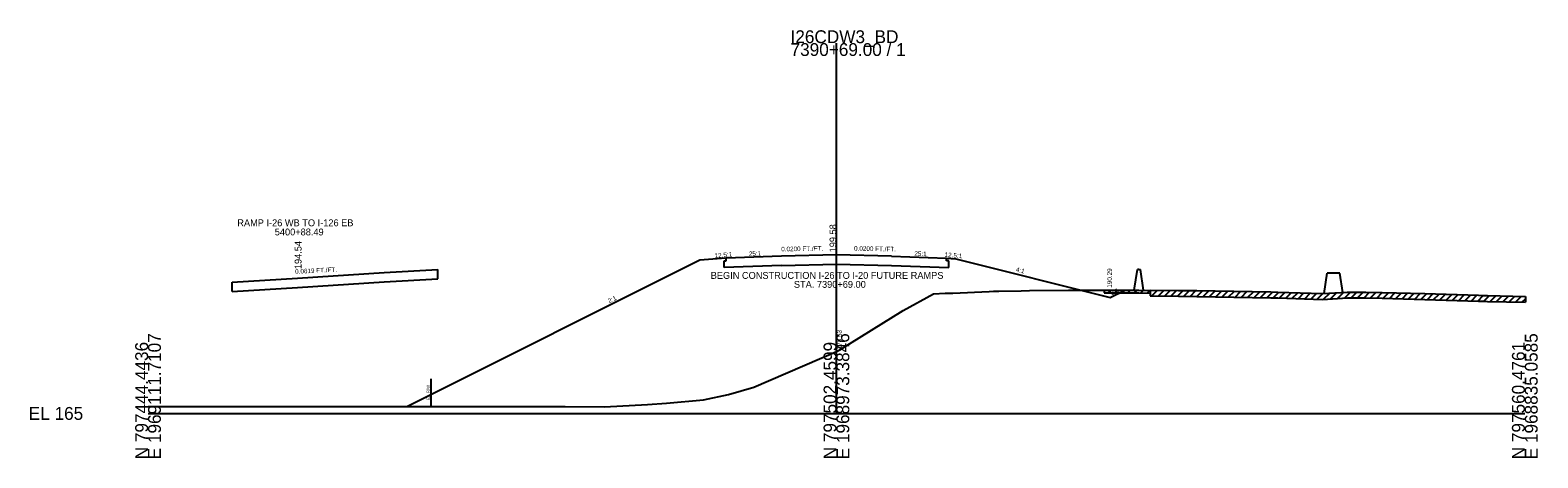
# Model space of a CAD drawing. Extents: x -26 to 1968923, y -11 to 797553.
# Drawn here: x 24.3 to 352.8, y -10.7 to 82.6 of the extents above; entities that cross this region are included whole.
import ezdxf

# ---------------------------------------------------------------- set-up
doc = ezdxf.new("R2010")
doc.units = 0
for name, color, linetype in [('RD_GPK_XS_Cell', 7, 'Continuous'), ('RD_XS_Base', 7, 'Continuous'), ('RD_XS_Bridge', 7, 'Continuous'), ('RD_XS_EarthShd', 7, 'Continuous'), ('RD_XS_ExGround', 7, 'Continuous'), ('RD_XS_ExPaveRet', 7, 'Continuous'), ('RD_XS_ExRW', 7, 'Continuous'), ('RD_XS_MedBWall', 7, 'Continuous'), ('RD_XS_Misc_Line', 7, 'Continuous'), ('RD_XS_Pave', 7, 'Continuous'), ('RD_XS_PaveShd', 7, 'Continuous'), ('RD_XS_TieSlope', 7, 'Continuous'), ('RD_XS_TX_Elev_EX', 7, 'Continuous'), ('RD_XS_TX_Elev_PR', 7, 'Continuous'), ('RD_XS_TX_Notes', 7, 'Continuous'), ('RD_XS_TX_Profile', 7, 'Continuous'), ('RD_XS_TX_ShdSlope', 7, 'Continuous'), ('RD_XS_TX_Slope', 7, 'Continuous'), ('RD_XS_TX_Station', 7, 'Continuous')]:
    doc.layers.add(name, color=color, linetype=linetype)

msp = doc.modelspace()

# ---------------------------------------------------------------- linework, layer by layer
at = {"layer": 'RD_GPK_XS_Cell'}
for p, q in [((200, -1), (200, 79.77)), ((50, -1), (200, -1)), ((200, -1), (350, -1))]:
    msp.add_line(p, q, dxfattribs=at)
at = {"layer": 'RD_XS_Base'}
for p, q in [((176, 32.3), (176, 32.86)), ((224, 32.3), (224, 32.86)), ((175.5, 32.28), (176, 32.3)), ((175.5, 30.8), (175.5, 32.28)), ((188, 31.3), (175.5, 30.8)), ((188, 31.3), (200, 31.54)), ((200, 31.54), (212, 31.3)), ((212, 31.3), (224.5, 30.8)), ((224.5, 32.28), (224, 32.3)), ((224.5, 30.8), (224.5, 32.28))]:
    msp.add_line(p, q, dxfattribs=at)
at = {"layer": 'RD_XS_Bridge'}
for p, q in [((82.57, 28.54), (101.43, 29.71)), ((101.43, 29.71), (113.12, 30.43)), ((113.12, 28.39), (113.12, 30.43)), ((68.3, 27.66), (82.57, 28.54)), ((68.3, 25.62), (68.3, 27.66)), ((68.3, 25.62), (82.57, 26.5)), ((82.57, 26.5), (101.43, 27.67)), ((101.43, 27.67), (113.12, 28.39))]:
    msp.add_line(p, q, dxfattribs=at)
at = {"layer": 'RD_XS_EarthShd'}
for p, q in [((176, 32.86), (174, 32.7)), ((224, 32.86), (226, 32.7))]:
    msp.add_line(p, q, dxfattribs=at)
at = {"layer": 'RD_XS_ExGround'}
msp.add_lwpolyline([(50, 0.54), (51.32, 0.54), (57.94, 0.54), (61.61, 0.54), (62.74, 0.54), (68.6, 0.54), (84.4, 0.54), (101.34, 0.54), (105.3, 0.54), (121.41, 0.54), (132.82, 0.54), (133.91, 0.54), (135.83, 0.54), (139.98, 0.54), (140.35, 0.54), (140.86, 0.53), (149.45, 0.46), (158.82, 0.95), (162.99, 1.27), (171.03, 2), (176.45, 3.1), (181.99, 4.7), (200, 12.53), (200.71, 12.84), (214.55, 21.44), (221.14, 25.06), (223.68, 25.21), (225.33, 25.26), (233.27, 25.63), (234.2, 25.68), (234.61, 25.69), (235.04, 25.69), (235.4, 25.68), (240.28, 25.75), (242.04, 25.79), (250.56, 25.9), (252.17, 25.9), (265.9, 25.92), (274.56, 25.8), (278.55, 25.79), (294.68, 25.49), (296.2, 25.48), (305.93, 25.13), (311.29, 25.46), (312.47, 25.48), (314.53, 25.46), (315.39, 25.45), (318.94, 25.37), (328.22, 25.13), (339.92, 24.77), (340.97, 24.73), (341.88, 24.7), (350.14, 24.49)], dxfattribs=at)
at = {"layer": 'RD_XS_ExPaveRet'}
for p, q in [((258.37, 25.91), (258.37, 25.29)), ((268.37, 25.89), (268.37, 24.64)), ((350.14, 24.49), (350.14, 23.24))]:
    msp.add_line(p, q, dxfattribs=at)
for points in [[(258.37, 25.29), (265.89, 25.3), (268.37, 25.26)], [(268.37, 24.64), (274.55, 24.55), (278.54, 24.54), (294.67, 24.24), (296.18, 24.23), (305.95, 23.88), (311.34, 24.21), (312.47, 24.23), (314.52, 24.21), (315.37, 24.2), (318.91, 24.12), (328.19, 23.88), (339.88, 23.52), (340.93, 23.48), (341.85, 23.45), (350.14, 23.24)]]:
    msp.add_lwpolyline(points, dxfattribs=at)
at = {"layer": 'RD_XS_ExRW'}
msp.add_line((111.6, 6.54), (111.6, 0.54), dxfattribs=at)
at = {"layer": 'RD_XS_MedBWall'}
for p, q in [((264.9, 25.92), (265.57, 30.4)), ((265.9, 30.4), (265.57, 30.4)), ((265.9, 30.4), (266.23, 30.4)), ((266.9, 25.92), (266.23, 30.4)), ((306.28, 25.15), (306.95, 29.63)), ((309.72, 29.63), (306.95, 29.63)), ((310.35, 25.4), (309.72, 29.63))]:
    msp.add_line(p, q, dxfattribs=at)
at = {"layer": 'RD_XS_Misc_Line'}
for p, q in [((258.37, 25.85), (258.43, 25.91)), ((259.22, 25.29), (259.85, 25.91)), ((260.64, 25.29), (261.27, 25.92)), ((262.06, 25.29), (262.68, 25.92)), ((263.47, 25.29), (264.1, 25.92)), ((264.89, 25.3), (265.52, 25.92)), ((266.3, 25.29), (266.92, 25.91)), ((267.7, 25.27), (268.31, 25.89)), ((268.37, 25.71), (268.55, 25.89)), ((268.71, 24.63), (269.95, 25.87)), ((270.11, 24.61), (271.34, 25.85)), ((271.5, 24.59), (272.73, 25.83)), ((272.9, 24.57), (274.13, 25.81)), ((274.29, 24.55), (275.53, 25.8)), ((275.7, 24.55), (276.94, 25.79)), ((277.11, 24.54), (278.35, 25.79)), ((278.52, 24.54), (279.74, 25.76)), ((279.9, 24.51), (281.13, 25.74)), ((281.29, 24.49), (282.52, 25.71)), ((282.68, 24.46), (283.91, 25.69)), ((284.07, 24.43), (285.3, 25.66)), ((285.46, 24.41), (286.68, 25.63)), ((286.85, 24.38), (288.07, 25.61)), ((288.23, 24.36), (289.46, 25.58)), ((289.62, 24.33), (290.85, 25.56)), ((291.01, 24.3), (292.24, 25.53)), ((292.4, 24.28), (293.63, 25.5)), ((293.79, 24.25), (295.02, 25.48)), ((295.18, 24.23), (296.42, 25.47)), ((296.58, 24.21), (297.78, 25.42)), ((297.94, 24.16), (299.15, 25.37)), ((299.31, 24.12), (300.52, 25.32)), ((300.67, 24.07), (301.88, 25.28)), ((302.04, 24.02), (303.25, 25.23)), ((303.41, 23.97), (304.61, 25.18)), ((304.77, 23.92), (305.99, 25.14)), ((306.16, 23.89), (307.49, 25.23)), ((307.66, 23.99), (309, 25.32)), ((309.17, 24.08), (310.5, 25.41)), ((310.68, 24.17), (311.98, 25.47)), ((312.15, 24.23), (313.39, 25.47)), ((313.56, 24.22), (314.79, 25.46)), ((314.96, 24.21), (316.18, 25.44)), ((316.34, 24.18), (317.56, 25.4)), ((317.72, 24.15), (318.95, 25.37)), ((319.1, 24.11), (320.32, 25.33)), ((320.48, 24.08), (321.7, 25.3)), ((321.86, 24.04), (323.08, 25.26)), ((323.24, 24.01), (324.46, 25.23)), ((324.62, 23.97), (325.84, 25.19)), ((326, 23.94), (327.22, 25.16)), ((327.38, 23.9), (328.6, 25.12)), ((328.76, 23.86), (329.97, 25.08)), ((330.13, 23.82), (331.34, 25.03)), ((331.5, 23.78), (332.71, 24.99)), ((332.87, 23.74), (334.08, 24.95)), ((334.24, 23.69), (335.45, 24.91)), ((335.61, 23.65), (336.82, 24.86)), ((336.98, 23.61), (338.2, 24.82)), ((338.35, 23.56), (339.57, 24.78)), ((339.73, 23.52), (340.94, 24.73)), ((341.1, 23.48), (342.31, 24.69)), ((342.47, 23.44), (343.69, 24.66)), ((343.85, 23.4), (345.07, 24.62)), ((345.23, 23.37), (346.45, 24.58)), ((346.6, 23.33), (347.82, 24.55)), ((347.98, 23.29), (349.2, 24.51)), ((349.36, 23.26), (350.14, 24.03))]:
    msp.add_line(p, q, dxfattribs=at)
at = {"layer": 'RD_XS_Pave'}
for p, q in [((200, 33.58), (188, 33.34)), ((212, 33.34), (200, 33.58))]:
    msp.add_line(p, q, dxfattribs=at)
at = {"layer": 'RD_XS_PaveShd'}
for p, q in [((188, 33.34), (176, 32.86)), ((212, 33.34), (224, 32.86))]:
    msp.add_line(p, q, dxfattribs=at)
at = {"layer": 'RD_XS_TieSlope'}
for p, q in [((170.25, 32.4), (106.52, 0.54)), ((174, 32.7), (170.25, 32.4)), ((226, 32.7), (259.67, 24.29)), ((259.67, 24.29), (262.94, 25.92))]:
    msp.add_line(p, q, dxfattribs=at)

# ---------------------------------------------------------------- texts
at = {"layer": 'RD_GPK_XS_Cell'}
for s, p in [('I26CDW3_BD', (190, 79.77)), ('7390+69.00 / 1', (190, 76.97)), ('EL 165', (24, -2.4))]:
    msp.add_text(s, height=2.8, dxfattribs=at).set_placement(p)
for s, p in [('N 797444.4436', (50, -11)), ('E 1969111.7107', (52.8, -11)), ('N 797502.4599', (200, -11)), ('E 1968973.3846', (202.8, -11)), ('N 797560.4761', (350, -11)), ('E 1968835.0585', (352.8, -11))]:
    msp.add_text(s, height=2.8, rotation=90, dxfattribs=at).set_placement(p)
at = {"layer": 'RD_XS_ExRW'}
msp.add_text('Ex. R/W ', height=0.65, rotation=90, dxfattribs=at).set_placement((111.35, 1.92))
at = {"layer": 'RD_XS_TX_Elev_EX'}
msp.add_text('178.53', height=1, rotation=90, dxfattribs=at).set_placement((201.13, 12.99))
at = {"layer": 'RD_XS_TX_Elev_PR'}
for s, p in [(' 199.58', (200, 33.58)), (' 194.54', (83.44, 29.92))]:
    msp.add_text(s, height=1.5, rotation=90, dxfattribs=at).set_placement(p)
at = {"layer": 'RD_XS_TX_Notes'}
for s, p in [('BEGIN CONSTRUCTION I-26 TO I-20 FUTURE RAMPS', (172.61, 28.36)), ('STA. 7390+69.00', (190.73, 26.4))]:
    msp.add_text(s, height=1.5, dxfattribs=at).set_placement(p)
at = {"layer": 'RD_XS_TX_Profile'}
for rotation, p in [(2.2906, (180.94, 33.31)), (357.7094, (216.96, 33.4))]:
    msp.add_text('25:1', height=1, rotation=rotation, dxfattribs=at).set_placement(p)
at = {"layer": 'RD_XS_TX_ShdSlope'}
for rotation, p in [(4.5739, (173.5, 32.91)), (355.4261, (223.54, 33.15))]:
    msp.add_text('12.5:1', height=1, rotation=rotation, dxfattribs=at).set_placement(p)
at = {"layer": 'RD_XS_TX_Slope'}
for s, rotation, p in [('0.0200 FT./FT.', 1.1458, (187.98, 34.34)), ('0.0200 FT./FT.', 358.8542, (203.83, 34.51)), ('0.0619 FT./FT.', 2.9412, (82.07, 29.45)), ('4:1', 345.9638, (239.03, 29.96)), ('190.29', 90, (260.02, 26.42)), ('2:1', 25.5405, (259.98, 24.75)), ('2:1', 25.5405, (150.47, 23))]:
    msp.add_text(s, height=1, rotation=rotation, dxfattribs=at).set_placement(p)
at = {"layer": 'RD_XS_TX_Station'}
for s, p in [('RAMP I-26 WB TO I-126 EB', (69.45, 39.83)), ('5400+88.49', (77.61, 37.83))]:
    msp.add_text(s, height=1.5, dxfattribs=at).set_placement(p)

doc.saveas('drawing.dxf')
